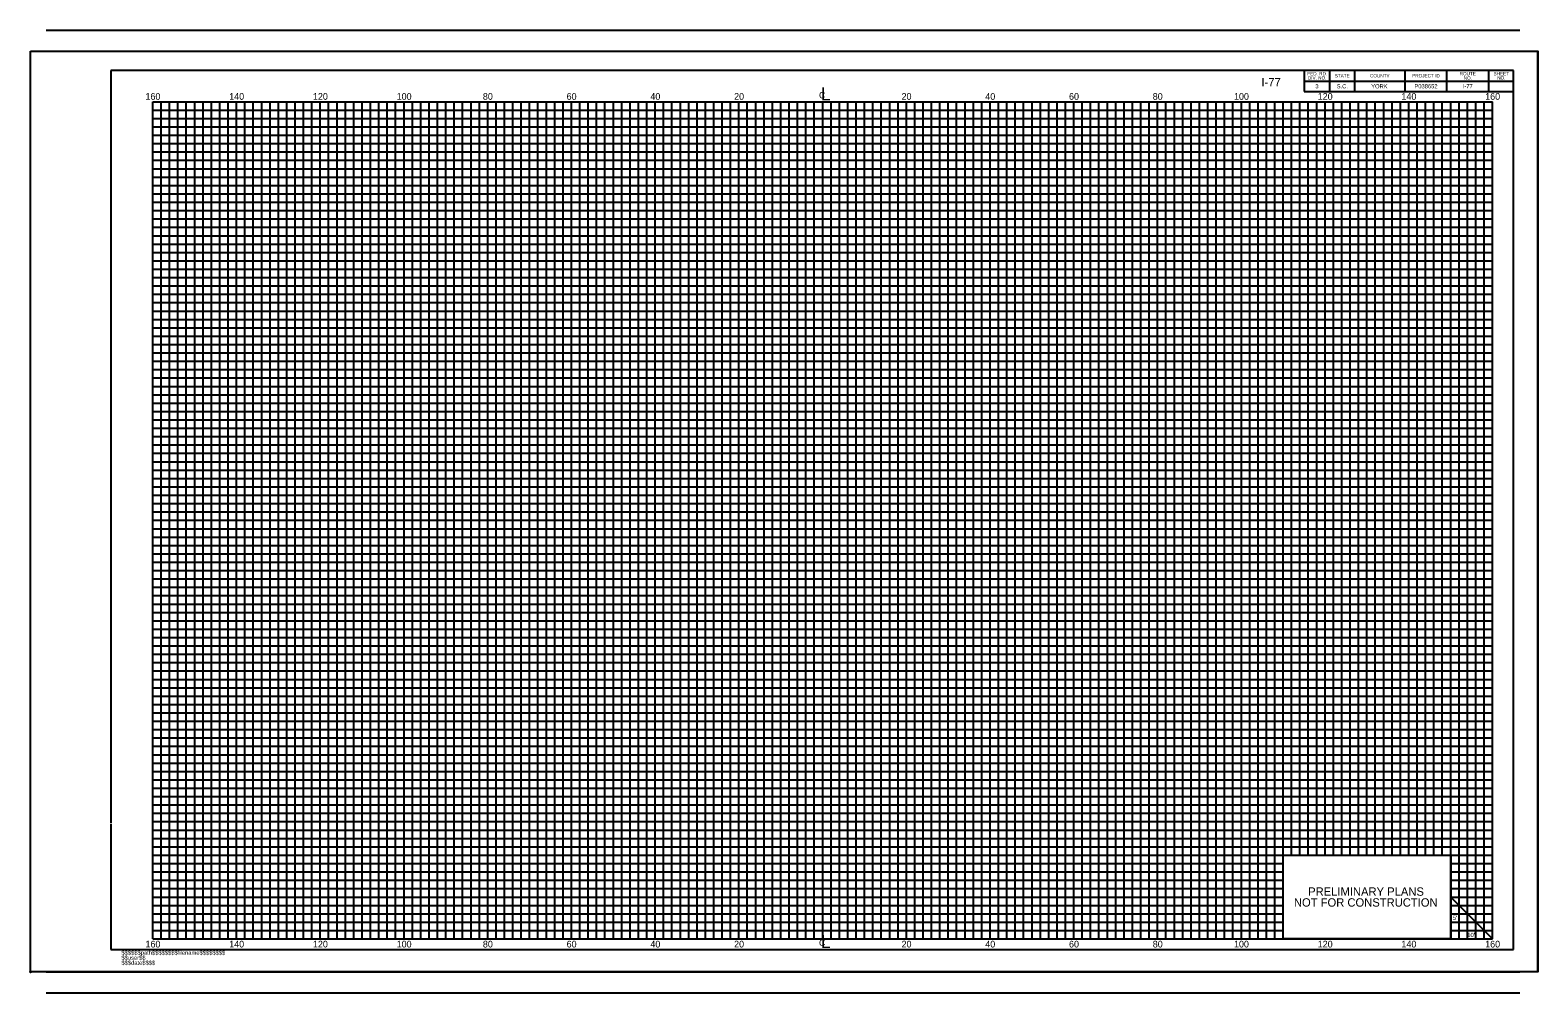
# Model space of a CAD drawing. Extents: x -15 to 165, y -6 to 109.
import ezdxf

# ---------------------------------------------------------------- set-up
doc = ezdxf.new("R2010")
doc.units = 0
for name, color, linetype in [('RD_DDB_StaTX', 7, 'Continuous'), ('RD_SHT_Bndy', 7, 'Continuous'), ('RD_SHT_ID', 7, 'Continuous'), ('RD_SHT_IplotShp', 7, 'Continuous'), ('RD_SHT_MjGrid_XS', 7, 'Continuous'), ('RD_SHT_MnGrid_XS', 7, 'Continuous'), ('RD_SHT_Snap', 7, 'Continuous'), ('RD_SHT_TX', 7, 'Continuous')]:
    doc.layers.add(name, color=color, linetype=linetype)

msp = doc.modelspace()

# ---------------------------------------------------------------- linework, layer by layer
at = {"layer": 'RD_SHT_Bndy'}
for p, q in [((-12.73, 108.55), (163.27, 108.55)), ((-12.73, 106.05), (163.27, 106.05)), ((-5, 103.72), (-5, 13.81)), ((162.51, 103.72), (-5, 103.72)), ((137.51, 103.72), (137.51, 101.22)), ((140.51, 103.72), (140.51, 101.22)), ((143.51, 103.72), (143.51, 101.22)), ((149.51, 103.72), (149.51, 101.22)), ((154.51, 103.72), (154.51, 101.22)), ((159.51, 103.72), (159.51, 101.22)), ((162.51, -1.28), (162.51, 103.72)), ((137.51, 102.47), (162.51, 102.47)), ((137.51, 101.22), (162.51, 101.22)), ((-5, 13.72), (-5, -1.28)), ((139.95, 5), (139.95, 5)), ((145, 5), (145, 5)), ((-5, -1.28), (162.51, -1.28)), ((-12.73, -3.95), (163.27, -3.95)), ((-12.73, -6.45), (163.27, -6.45))]:
    msp.add_line(p, q, dxfattribs=at)
msp.add_lwpolyline([(135, 10), (155, 10), (155, 0), (135, 0)], close=True, dxfattribs=at)
at = {"layer": 'RD_SHT_IplotShp'}
msp.add_lwpolyline([(-14.59, 106.05), (165.41, 106.05), (165.41, -3.95), (-14.59, -3.95)], close=True, dxfattribs=at)
at = {"layer": 'RD_SHT_MjGrid_XS'}
for p, q in [((0, 100), (160, 100)), ((0, 0), (0, 100)), ((5, 0), (5, 100)), ((10, 0), (10, 100)), ((15, 0), (15, 100)), ((20, 0), (20, 100)), ((25, 0), (25, 100)), ((30, 0), (30, 100)), ((35, 0), (35, 100)), ((40, 0), (40, 100)), ((45, 0), (45, 100)), ((50, 0), (50, 100)), ((55, 0), (55, 100)), ((60, 0), (60, 100)), ((65, 0), (65, 100)), ((70, 0), (70, 100)), ((75, 0), (75, 100)), ((80, 0), (80, 100)), ((85, 0), (85, 100)), ((90, 0), (90, 100)), ((95, 0), (95, 100)), ((100, 0), (100, 100)), ((105, 0), (105, 100)), ((110, 0), (110, 100)), ((115, 0), (115, 100)), ((120, 0), (120, 100)), ((125, 0), (125, 100)), ((130, 0), (130, 100)), ((135, 0), (135, 100)), ((140, 10), (140, 100)), ((145, 10), (145, 100)), ((150, 10), (150, 100)), ((155, 0), (155, 100)), ((160, 0), (160, 100)), ((0, 95), (160, 95)), ((0, 90), (160, 90)), ((0, 85), (160, 85)), ((0, 80), (160, 80)), ((0, 75), (160, 75)), ((0, 70), (160, 70)), ((0, 65), (160, 65)), ((0, 60), (160, 60)), ((0, 55), (160, 55)), ((0, 50), (160, 50)), ((0, 45), (160, 45)), ((0, 40), (160, 40)), ((0, 35), (160, 35)), ((0, 30), (160, 30)), ((0, 25), (160, 25)), ((0, 20), (160, 20)), ((0, 15), (160, 15)), ((0, 10), (160, 10)), ((0, 5), (135, 5)), ((155, 5), (160, 0)), ((155, 5), (160, 5)), ((0, 0), (160, 0))]:
    msp.add_line(p, q, dxfattribs=at)
at = {"layer": 'RD_SHT_MnGrid_XS'}
for p, q in [((1, 0), (1, 100)), ((2, 0), (2, 100)), ((3, 0), (3, 100)), ((4, 0), (4, 100)), ((6, 0), (6, 100)), ((7, 0), (7, 100)), ((8, 0), (8, 100)), ((9, 0), (9, 100)), ((11, 0), (11, 100)), ((12, 0), (12, 100)), ((13, 0), (13, 100)), ((14, 0), (14, 100)), ((16, 0), (16, 100)), ((17, 0), (17, 100)), ((18, 0), (18, 100)), ((19, 0), (19, 100)), ((21, 0), (21, 100)), ((22, 0), (22, 100)), ((23, 0), (23, 100)), ((24, 0), (24, 100)), ((26, 0), (26, 100)), ((27, 0), (27, 100)), ((28, 0), (28, 100)), ((29, 0), (29, 100)), ((31, 0), (31, 100)), ((32, 0), (32, 100)), ((33, 0), (33, 100)), ((34, 0), (34, 100)), ((36, 0), (36, 100)), ((37, 0), (37, 100)), ((38, 0), (38, 100)), ((39, 0), (39, 100)), ((41, 0), (41, 100)), ((42, 0), (42, 100)), ((43, 0), (43, 100)), ((44, 0), (44, 100)), ((46, 0), (46, 100)), ((47, 0), (47, 100)), ((48, 0), (48, 100)), ((49, 0), (49, 100)), ((51, 0), (51, 100)), ((52, 0), (52, 100)), ((53, 0), (53, 100)), ((54, 0), (54, 100)), ((56, 0), (56, 100)), ((57, 0), (57, 100)), ((58, 0), (58, 100)), ((59, 0), (59, 100)), ((61, 0), (61, 100)), ((62, 0), (62, 100)), ((63, 0), (63, 100)), ((64, 0), (64, 100)), ((66, 0), (66, 100)), ((67, 0), (67, 100)), ((68, 0), (68, 100)), ((69, 0), (69, 100)), ((71, 0), (71, 100)), ((72, 0), (72, 100)), ((73, 0), (73, 100)), ((74, 0), (74, 100)), ((76, 0), (76, 100)), ((77, 0), (77, 100)), ((78, 0), (78, 100)), ((79, 0), (79, 100)), ((81, 0), (81, 100)), ((82, 0), (82, 100)), ((83, 0), (83, 100)), ((84, 0), (84, 100)), ((86, 0), (86, 100)), ((87, 0), (87, 100)), ((88, 0), (88, 100)), ((89, 0), (89, 100)), ((91, 0), (91, 100)), ((92, 0), (92, 100)), ((93, 0), (93, 100)), ((94, 0), (94, 100)), ((96, 0), (96, 100)), ((97, 0), (97, 100)), ((98, 0), (98, 100)), ((99, 0), (99, 100)), ((101, 0), (101, 100)), ((102, 0), (102, 100)), ((103, 0), (103, 100)), ((104, 0), (104, 100)), ((106, 0), (106, 100)), ((107, 0), (107, 100)), ((108, 0), (108, 100)), ((109, 0), (109, 100)), ((111, 0), (111, 100)), ((112, 0), (112, 100)), ((113, 0), (113, 100)), ((114, 0), (114, 100)), ((116, 0), (116, 100)), ((117, 0), (117, 100)), ((118, 0), (118, 100)), ((119, 0), (119, 100)), ((121, 0), (121, 100)), ((122, 0), (122, 100)), ((123, 0), (123, 100)), ((124, 0), (124, 100)), ((126, 0), (126, 100)), ((127, 0), (127, 100)), ((128, 0), (128, 100)), ((129, 0), (129, 100)), ((131, 0), (131, 100)), ((132, 0), (132, 100)), ((133, 0), (133, 100)), ((134, 0), (134, 100)), ((136, 10), (136, 100)), ((137, 10), (137, 100)), ((138, 10), (138, 100)), ((139, 10), (139, 100)), ((141, 10), (141, 100)), ((142, 10), (142, 100)), ((143, 10), (143, 100)), ((144, 10), (144, 100)), ((146, 10), (146, 100)), ((147, 10), (147, 100)), ((148, 10), (148, 100)), ((149, 10), (149, 100)), ((151, 10), (151, 100)), ((152, 10), (152, 100)), ((153, 10), (153, 100)), ((154, 10), (154, 100)), ((156, 0), (156, 100)), ((157, 0), (157, 100)), ((158, 0), (158, 100)), ((159, 0), (159, 100)), ((0, 99), (160, 99)), ((0, 98), (160, 98)), ((0, 97), (160, 97)), ((0, 96), (160, 96)), ((0, 94), (160, 94)), ((0, 93), (160, 93)), ((0, 92), (160, 92)), ((0, 91), (160, 91)), ((0, 89), (160, 89)), ((0, 88), (160, 88)), ((0, 87), (160, 87)), ((0, 86), (160, 86)), ((0, 84), (160, 84)), ((0, 83), (160, 83)), ((0, 82), (160, 82)), ((0, 81), (160, 81)), ((0, 79), (160, 79)), ((0, 78), (160, 78)), ((0, 77), (160, 77)), ((0, 76), (160, 76)), ((0, 74), (160, 74)), ((0, 73), (160, 73)), ((0, 72), (160, 72)), ((0, 71), (160, 71)), ((0, 69), (160, 69)), ((0, 68), (160, 68)), ((0, 67), (160, 67)), ((0, 66), (160, 66)), ((0, 64), (160, 64)), ((0, 63), (160, 63)), ((0, 62), (160, 62)), ((0, 61), (160, 61)), ((0, 59), (160, 59)), ((0, 58), (160, 58)), ((0, 57), (160, 57)), ((0, 56), (160, 56)), ((0, 54), (160, 54)), ((0, 53), (160, 53)), ((0, 52), (160, 52)), ((0, 51), (160, 51)), ((0, 49), (160, 49)), ((0, 48), (160, 48)), ((0, 47), (160, 47)), ((0, 46), (160, 46)), ((0, 44), (160, 44)), ((0, 43), (160, 43)), ((0, 42), (160, 42)), ((0, 41), (160, 41)), ((0, 39), (160, 39)), ((0, 38), (160, 38)), ((0, 37), (160, 37)), ((0, 36), (160, 36)), ((0, 34), (160, 34)), ((0, 33), (160, 33)), ((0, 32), (160, 32)), ((0, 31), (160, 31)), ((0, 29), (160, 29)), ((0, 28), (160, 28)), ((0, 27), (160, 27)), ((0, 26), (160, 26)), ((0, 24), (160, 24)), ((0, 23), (160, 23)), ((0, 22), (160, 22)), ((0, 21), (160, 21)), ((0, 21), (160, 21)), ((0, 19), (160, 19)), ((0, 18), (160, 18)), ((0, 17), (160, 17)), ((0, 16), (160, 16)), ((0, 14), (160, 14)), ((0, 13), (160, 13)), ((0, 12), (160, 12)), ((0, 11), (160, 11)), ((0, 9), (135, 9)), ((0, 8), (135, 8)), ((155, 9), (160, 9)), ((155, 8), (160, 8)), ((0, 7), (135, 7)), ((0, 6), (135, 6)), ((155, 7), (160, 7)), ((155, 6), (160, 6)), ((0, 4), (135, 4)), ((155, 4), (160, 4)), ((0, 3), (135, 3)), ((0, 2), (135, 2)), ((155, 3), (160, 3)), ((155, 2), (160, 2)), ((0, 1), (135, 1)), ((155, 1), (160, 1))]:
    msp.add_line(p, q, dxfattribs=at)
at = {"layer": 'RD_SHT_Snap'}
for p, q in [((-14.59, -3.95), (-14.59, 106.05)), ((165.41, -3.95), (165.41, 106.05))]:
    msp.add_line(p, q, dxfattribs=at)
msp.add_circle((-14.59, -3.95), 0.0607, dxfattribs=at)

# ---------------------------------------------------------------- texts
at = {"layer": 'RD_DDB_StaTX'}
for s, height, p in [('160', 0.8, (-0.88, 100.23)), ('140', 0.8, (9.12, 100.23)), ('120', 0.8, (19.12, 100.23)), ('100', 0.8, (29.12, 100.23)), ('80', 0.8, (39.42, 100.23)), ('60', 0.8, (49.42, 100.23)), ('40', 0.8, (59.42, 100.23)), ('20', 0.8, (69.42, 100.23)), ('C', 0.773, (79.56, 100.4)), ('L', 1.55, (79.79, 100.16)), ('20', 0.8, (89.42, 100.23)), ('40', 0.8, (99.42, 100.23)), ('60', 0.8, (109.42, 100.23)), ('80', 0.8, (119.42, 100.23)), ('100', 0.8, (129.12, 100.23)), ('120', 0.8, (139.12, 100.23)), ('140', 0.8, (149.12, 100.23)), ('160', 0.8, (159.12, 100.23)), ('L', 1.55, (79.79, -1.09)), ('160', 0.8, (-0.88, -1.03)), ('140', 0.8, (9.12, -1.03)), ('120', 0.8, (19.12, -1.03)), ('100', 0.8, (29.12, -1.03)), ('80', 0.8, (39.42, -1.03)), ('60', 0.8, (49.42, -1.03)), ('40', 0.8, (59.42, -1.03)), ('20', 0.8, (69.42, -1.03)), ('C', 0.773, (79.56, -0.85)), ('20', 0.8, (89.42, -1.03)), ('40', 0.8, (99.42, -1.03)), ('60', 0.8, (109.42, -1.03)), ('80', 0.8, (119.42, -1.03)), ('100', 0.8, (129.12, -1.03)), ('120', 0.8, (139.12, -1.03)), ('140', 0.8, (149.12, -1.03)), ('160', 0.8, (159.12, -1.03))]:
    msp.add_text(s, height=height, dxfattribs=at).set_placement(p)
at = {"layer": 'RD_SHT_ID'}
for s, p in [('$$$$$$path$$$$$$$$filename$$$$$$$$', (-3.75, -1.9)), ('$$user$$', (-3.75, -2.5)), ('$$$date$$$$', (-3.75, -3.1))]:
    msp.add_text(s, height=0.5, rotation=360, dxfattribs=at).set_placement(p)
at = {"layer": 'RD_SHT_TX'}
for s, height, p in [('I-77', 1, (132.4, 101.83)), ('FED. RD.', 0.4, (137.88, 103.15)), ('DIV. NO.', 0.4, (137.95, 102.65)), ('STATE', 0.4, (141.15, 102.9)), ('COUNTY', 0.4, (145.37, 102.9)), ('PROJECT ID', 0.4, (150.41, 102.9)), ('ROUTE', 0.4, (156.07, 103.15)), ('NO.', 0.4, (156.56, 102.63)), ('SHEET', 0.4, (160.12, 103.15)), ('NO.', 0.4, (160.56, 102.65)), ('3', 0.5, (138.84, 101.6)), ('S.C.', 0.5, (141.39, 101.6)), ('YORK', 0.5, (145.51, 101.6)), ('P038652', 0.5, (150.67, 101.6)), ('I-77', 0.5, (156.44, 101.6)), ('PRELIMINARY PLANS', 1, (137.98, 5.15)), ('NOT FOR CONSTRUCTION', 1, (136.28, 3.85)), ("5'", 0.512, (155.26, 2.26)), ("10'", 0.512, (156.97, 0.21))]:
    msp.add_text(s, height=height, dxfattribs=at).set_placement(p)

doc.saveas('drawing.dxf')
